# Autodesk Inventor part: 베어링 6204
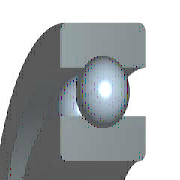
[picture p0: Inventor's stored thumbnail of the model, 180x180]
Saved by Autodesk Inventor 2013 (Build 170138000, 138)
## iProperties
Created: 2012-02
Part Number: 베어링 6204
Material: 강철, 연강
Description: 깊은 그루브 볼 베어링
Document SubType Name: Modeling
Standard: KS B 2023
Designer: mduedu
Standards Organization: KS
Language: ko-KR
Size Designation: 6204 - 20 x 47 x 14
Categories: <MemberInstance><Categories><Category DisplayName="샤프트 부품" InternalName="7f7aeb1f-a693-4053-b835-cee3144e0d98" Mnemonic="SHFT"><Category DisplayName="베어링" Inter
Density: 1 g/cm^3
IsCustomPart: 1
Author: mduedu
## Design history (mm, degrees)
sketch "스케치" dims "d0" = 7.02 (= -0.26 x WD + 0.26 x BD)
  geometry: L1 (3.49, 16.75)-(10.51, 16.75); L2 (7, 16.75)-(7, 13.24); L3 (7, 16.75)-(7, 20.26); L4 (4.392, 14.401)-(0, 14.401); L5 (0, 10)-(14, 10); L6 (4.392, 19.099)-(0, 19.099); L7 (0, 23.5)-(14, 23.5); L8 (14, 10)-(14, 14.401); L9 (9.608, 14.401)-(14, 14.401); L10 (9.608, 19.099)-(14, 19.099); L11 (14, 23.5)-(14, 19.099); L12 (-1.4, 0)-(8.4, 0) reference; L13 (0, -0.3)-(0, 5.3) reference
  constraints: 22 end point, 4 point on line, 2 collinear, 2 perpendicular, 2 symmetric about line, 1 midpoint, 1 parallel, 14 other
  dimensions: "d9" = 20 diameter of L5 L12 (= WD); "d11" = 47 diameter of L7 L12 (= BD); "d12" = 14 distance between parallel lines of L8 L13 (= KB); "d13" = 28.802 diameter of L9 L12 (= 0.326 x BD + 0.674 x WD)
revolve "본체" stored, may be unused: angle "d6" = 90 deg
revolve "볼" stored, may be unused: angle "d7" = 90 deg
pattern_circular "IDS_ARRAYBALL[SIMPL:T]" dims angle "d3" = 360 deg
body "Solid1"
fillet "모깎기1" dims "d1" = 1 (= KRS)
other parameters: "WD" = 20 [user parameter; used in 5 equation terms], "BD" = 47 [user parameter; used in 5 equation terms], "KB" = 14 [user parameter; used in 1 equation term], "KRS" = 1 [user parameter; used in 1 equation term], "d4" = 0, "d5" = 0, "d8" = 0, "d14" = 0, "d15" = 0, "BBA" = 0 [user parameter], "BC0" = 6550000 [user parameter], "BC" = 1.27e+07 [user parameter], "BR" = 23.5 (= 0.5 x BD) [user parameter]
